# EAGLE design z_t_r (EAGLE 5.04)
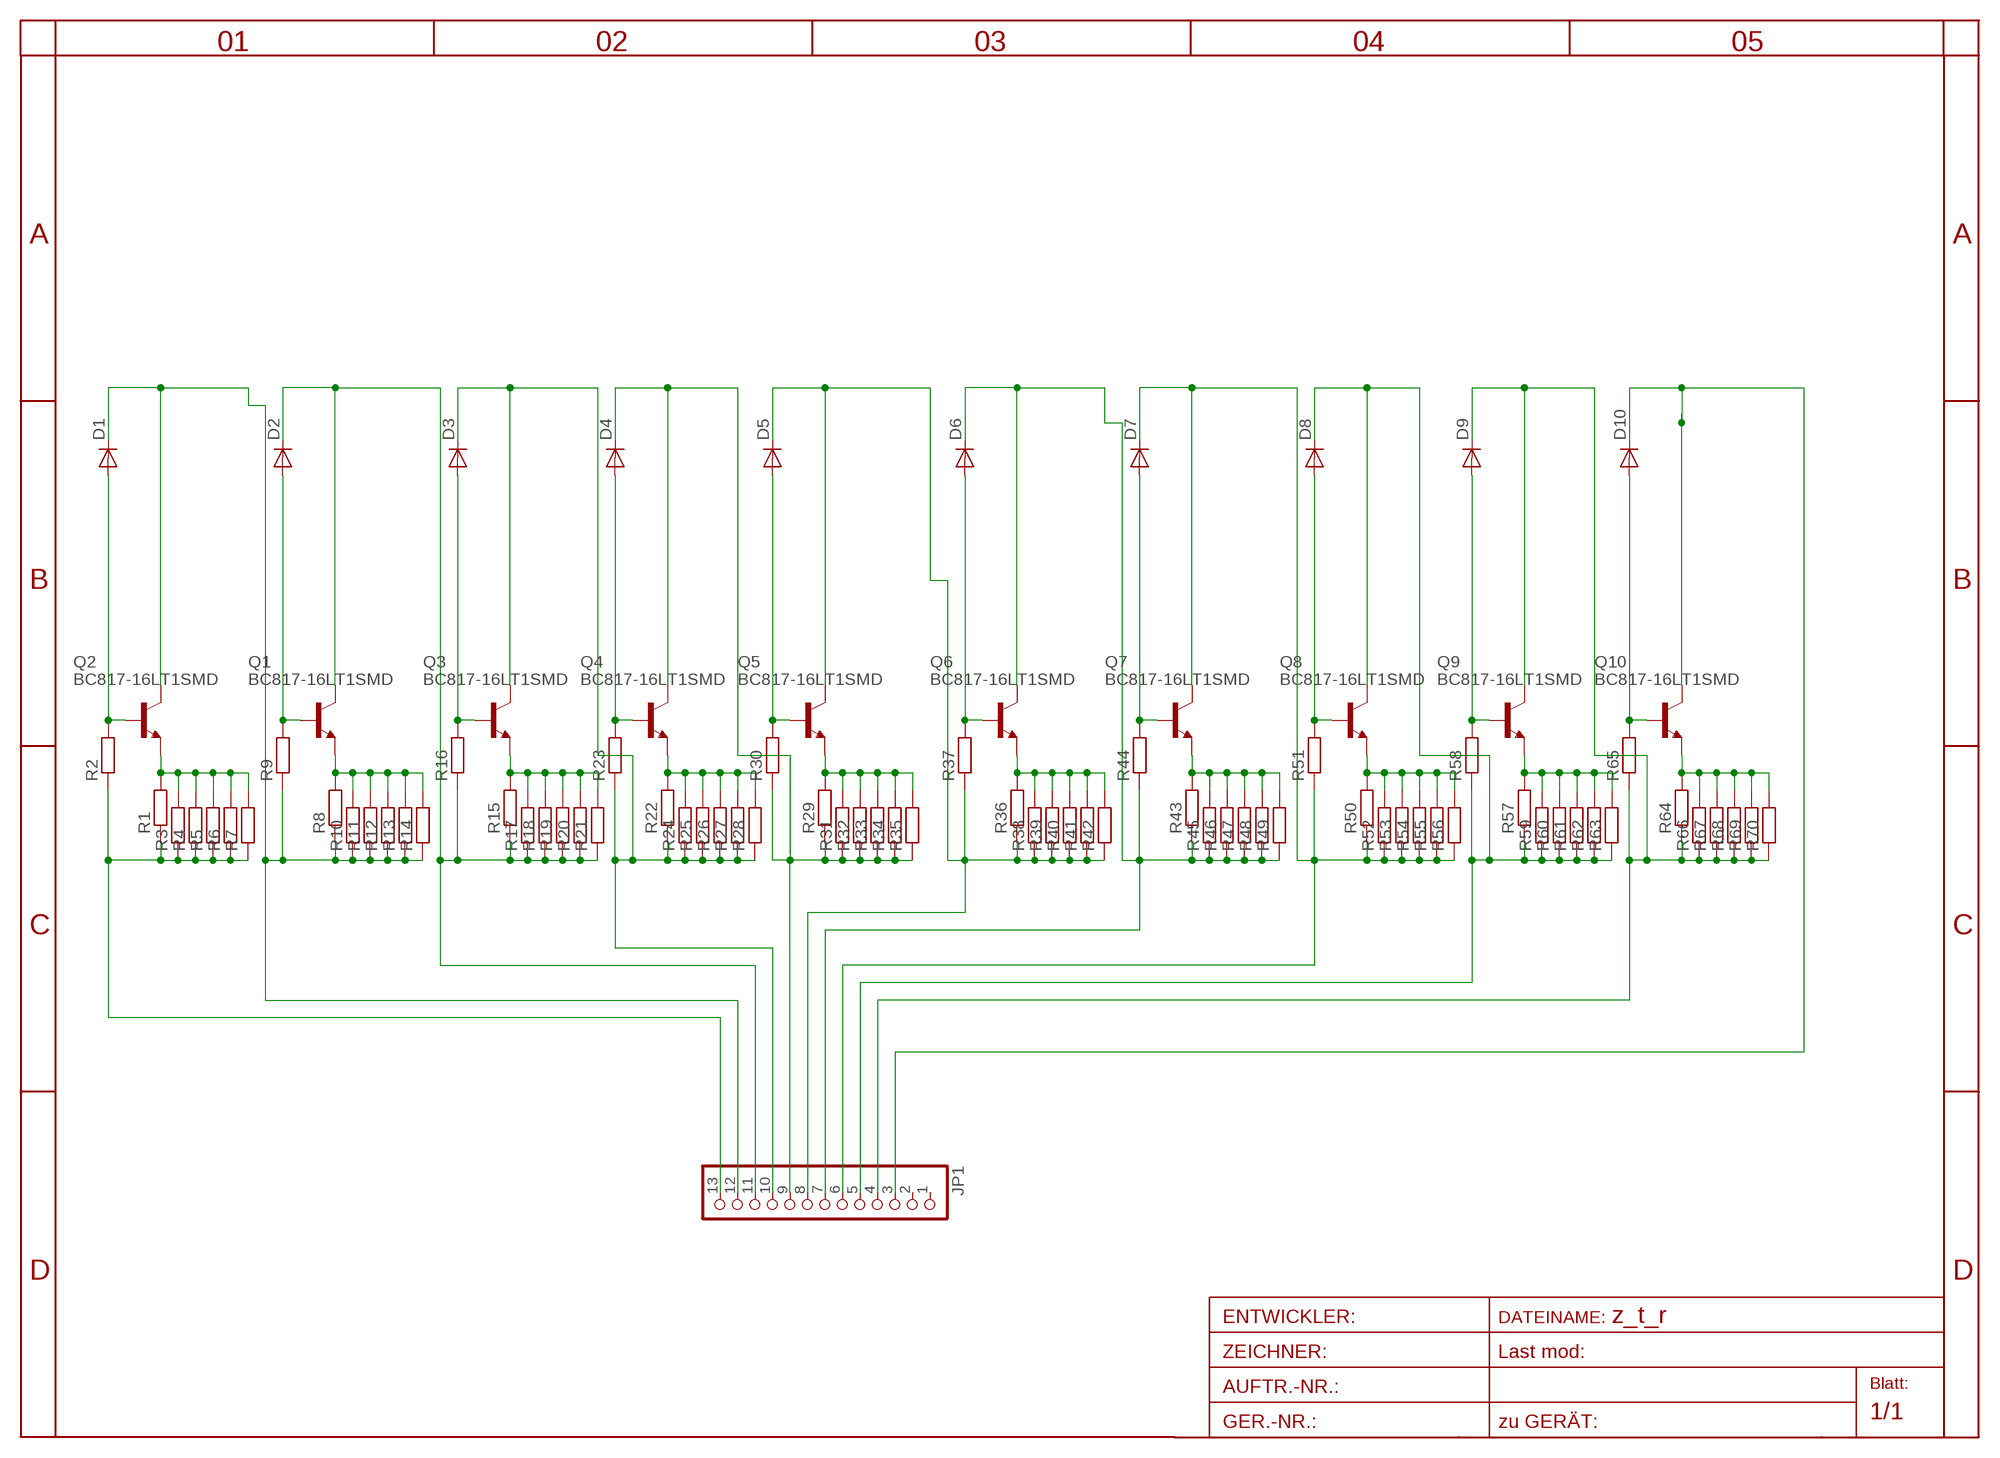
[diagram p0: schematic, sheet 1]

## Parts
D1  DIODE-MINIMELF  [MINIMELF]
D2  DIODE-MINIMELF  [MINIMELF]
D3  DIODE-MINIMELF  [MINIMELF]
D4  DIODE-MINIMELF  [MINIMELF]
D5  DIODE-MINIMELF  [MINIMELF]
D6  DIODE-MINIMELF  [MINIMELF]
D7  DIODE-MINIMELF  [MINIMELF]
D8  DIODE-MINIMELF  [MINIMELF]
D9  DIODE-MINIMELF  [MINIMELF]
D10  DIODE-MINIMELF  [MINIMELF]
JP1  PINHD-1X13  [1X13]
Q1  BC817-16LT1SMD  [SOT23-BEC]
Q2  BC817-16LT1SMD  [SOT23-BEC]
Q3  BC817-16LT1SMD  [SOT23-BEC]
Q4  BC817-16LT1SMD  [SOT23-BEC]
Q5  BC817-16LT1SMD  [SOT23-BEC]
Q6  BC817-16LT1SMD  [SOT23-BEC]
Q7  BC817-16LT1SMD  [SOT23-BEC]
Q8  BC817-16LT1SMD  [SOT23-BEC]
Q9  BC817-16LT1SMD  [SOT23-BEC]
Q10  BC817-16LT1SMD  [SOT23-BEC]
R1  R-EU_R1206  [R1206]
R2  R-EU_R0805  [R0805]
R3  R-EU_R1206  [R1206]
R4  R-EU_R1206  [R1206]
R5  R-EU_R1206  [R1206]
R6  R-EU_R1206  [R1206]
R7  R-EU_R1206  [R1206]
R8  R-EU_R1206  [R1206]
R9  R-EU_R0805  [R0805]
R10  R-EU_R1206  [R1206]
R11  R-EU_R1206  [R1206]
R12  R-EU_R1206  [R1206]
R13  R-EU_R1206  [R1206]
R14  R-EU_R1206  [R1206]
R15  R-EU_R1206  [R1206]
R16  R-EU_R0805  [R0805]
R17  R-EU_R1206  [R1206]
R18  R-EU_R1206  [R1206]
R19  R-EU_R1206  [R1206]
R20  R-EU_R1206  [R1206]
R21  R-EU_R1206  [R1206]
R22  R-EU_R1206  [R1206]
R23  R-EU_R0805  [R0805]
R24  R-EU_R1206  [R1206]
R25  R-EU_R1206  [R1206]
R26  R-EU_R1206  [R1206]
R27  R-EU_R1206  [R1206]
R28  R-EU_R1206  [R1206]
R29  R-EU_R1206  [R1206]
R30  R-EU_R0805  [R0805]
R31  R-EU_R1206  [R1206]
R32  R-EU_R1206  [R1206]
R33  R-EU_R1206  [R1206]
R34  R-EU_R1206  [R1206]
R35  R-EU_R1206  [R1206]
R36  R-EU_R1206  [R1206]
R37  R-EU_R0805  [R0805]
R38  R-EU_R1206  [R1206]
R39  R-EU_R1206  [R1206]
R40  R-EU_R1206  [R1206]
R41  R-EU_R1206  [R1206]
R42  R-EU_R1206  [R1206]
R43  R-EU_R1206  [R1206]
R44  R-EU_R0805  [R0805]
R45  R-EU_R1206  [R1206]
R46  R-EU_R1206  [R1206]
R47  R-EU_R1206  [R1206]
R48  R-EU_R1206  [R1206]
R49  R-EU_R1206  [R1206]
R50  R-EU_R1206  [R1206]
R51  R-EU_R0805  [R0805]
R52  R-EU_R1206  [R1206]
R53  R-EU_R1206  [R1206]
R54  R-EU_R1206  [R1206]
R55  R-EU_R1206  [R1206]
R56  R-EU_R1206  [R1206]
R57  R-EU_R1206  [R1206]
R58  R-EU_R0805  [R0805]
R59  R-EU_R1206  [R1206]
R60  R-EU_R1206  [R1206]
R61  R-EU_R1206  [R1206]
R62  R-EU_R1206  [R1206]
R63  R-EU_R1206  [R1206]
R64  R-EU_R1206  [R1206]
R65  R-EU_R0805  [R0805]
R66  R-EU_R1206  [R1206]
R67  R-EU_R1206  [R1206]
R68  R-EU_R1206  [R1206]
R69  R-EU_R1206  [R1206]
R70  R-EU_R1206  [R1206]

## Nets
B1: D1.C JP1.12 Q2.C R8.1 R9.1 R10.1 R11.1 R12.1 R13.1 R14.1
B2: D2.C JP1.11 Q1.C R15.1 R16.1 R17.1 R18.1 R19.1 R20.1 R21.1
B3: D3.C JP1.10 Q3.C R22.1 R23.1 R24.1 R25.1 R26.1 R27.1 R28.1
B4: D4.C JP1.9 Q4.C R29.1 R30.1 R31.1 R32.1 R33.1 R34.1 R35.1
B5: D5.C JP1.8 Q5.C R36.1 R37.1 R38.1 R39.1 R40.1 R41.1 R42.1
B6: D6.C JP1.7 Q6.C R43.1 R44.1 R45.1 R46.1 R47.1 R48.1 R49.1
B7: D7.C JP1.6 Q7.C R50.1 R51.1 R52.1 R53.1 R54.1 R55.1 R56.1
B8: D8.C JP1.5 Q8.C R57.1 R58.1 R59.1 R60.1 R61.1 R62.1 R63.1
B9: D9.C JP1.4 Q9.C R64.1 R65.1 R66.1 R67.1 R68.1 R69.1 R70.1
B10: D10.C JP1.3 Q10.C
B-: JP1.13 R1.1 R2.1 R3.1 R4.1 R5.1 R6.1 R7.1
D0: D1.A Q2.B R2.2
D1: D2.A Q1.B R9.2
D2: D3.A Q3.B R16.2
D3: D4.A Q4.B R23.2
D4: D5.A Q5.B R30.2
D5: D6.A Q6.B R37.2
D6: D7.A Q7.B R44.2
D7: D8.A Q8.B R51.2
D8: D9.A Q9.B R58.2
D9: D10.A Q10.B R65.2
N$2: Q2.E R1.2 R3.2 R4.2 R5.2 R6.2 R7.2
N$3: Q1.E R8.2 R10.2 R11.2 R12.2 R13.2 R14.2
N$6: Q3.E R15.2 R17.2 R18.2 R19.2 R20.2 R21.2
N$8: Q4.E R22.2 R24.2 R25.2 R26.2 R27.2 R28.2
N$10: Q5.E R29.2 R31.2 R32.2 R33.2 R34.2 R35.2
N$12: Q6.E R36.2 R38.2 R39.2 R40.2 R41.2 R42.2
N$14: Q7.E R43.2 R45.2 R46.2 R47.2 R48.2 R49.2
N$16: Q8.E R50.2 R52.2 R53.2 R54.2 R55.2 R56.2
N$18: Q9.E R57.2 R59.2 R60.2 R61.2 R62.2 R63.2
N$20: Q10.E R64.2 R66.2 R67.2 R68.2 R69.2 R70.2
Unconnected: JP1.1 JP1.2

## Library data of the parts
D1-D10 = diode-1:DIODE-: DIODE
JP1 = pinhead(2):PINHD-1X13: PIN HEADER
Q1-Q10 = transistor-npn:BC817*: NPN Transistor
R1-R70 = rcl-2:R-EU_: RESISTOR, European symbol

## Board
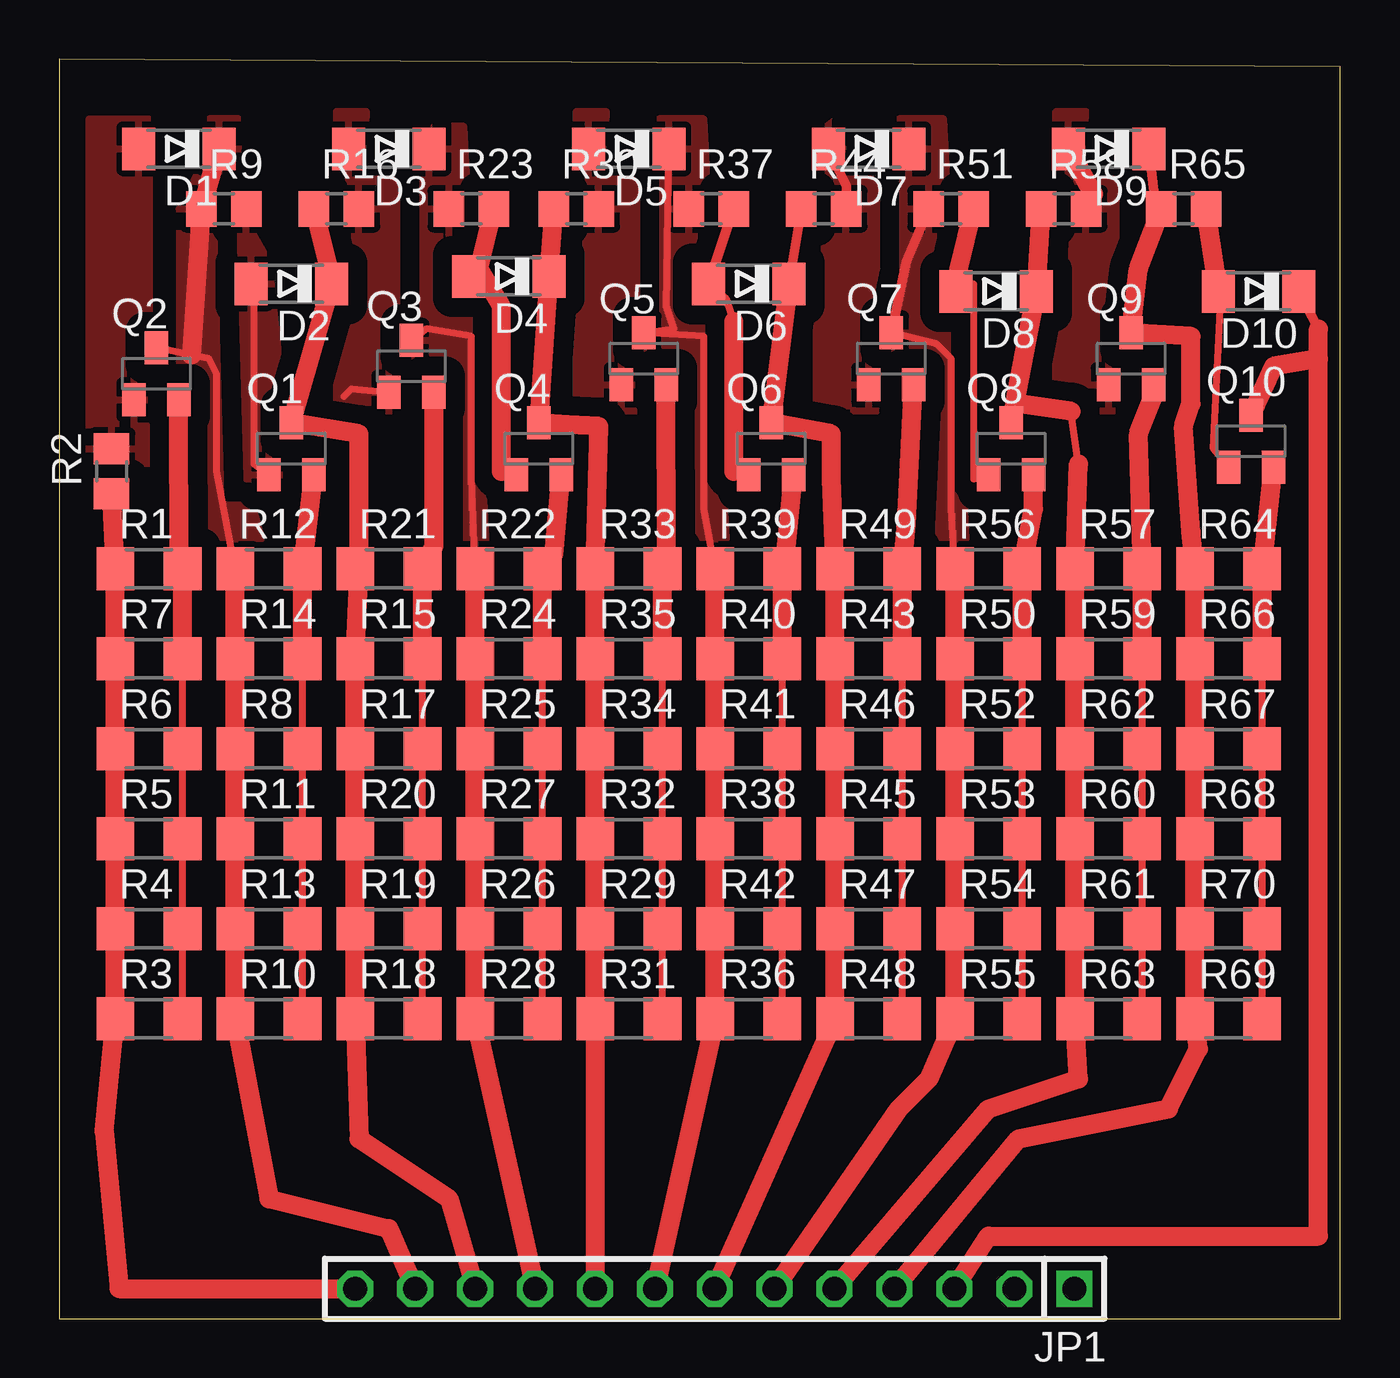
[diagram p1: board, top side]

Size 54.27 x 53.33 mm. Coordinates in mm from the lower left corner, seen from the top.
Outline: 0,0 54.27,0 54.27,53 0,53.33 0,0
Copper layers (1*16): Top 0.035mm / dielectric 1.5mm / Bottom 0.035mm
Design rules "default": minimum track width 10mil, minimum drill 24mil, track to track 8mil, track to pad 8mil, pad to pad 8mil, via to via 8mil, smd to smd 8mil, copper to edge 40mil, drill to drill 8mil, minimum pad ring 10mil, minimum via ring 8mil, stop-mask expansion 4mil, vias tented up to drill 0mil, thermal gap 10mil

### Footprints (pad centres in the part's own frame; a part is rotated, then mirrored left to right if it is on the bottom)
MINIMELF = smd 1.4 x 1.8: A 1.7,0; C -1.7,0
1X13 = drill 1.016 square: 1 -15.24,0 | drill 1.016 octagon: 2 -12.7,0; 3 -10.16,0; 4 -7.62,0; 5 -5.08,0; 6 -2.54,0; 7 0,0; 8 2.54,0; 9 5.08,0; 10 7.62,0; 11 10.16,0; 12 12.7,0; 13 15.24,0
SOT23-BEC = smd 1 x 1.4: B -0.95,-1.1; C 0,1.1; E 0.95,-1.1
R1206 = smd 1.6 x 1.803: 1 -1.422,0; 2 1.422,0
R0805 = smd 1.3 x 1.5: 1 -0.95,0; 2 0.95,0

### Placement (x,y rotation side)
D1  5.08,49.53 180 top
D2  9.84,43.81 180 top
D3  13.97,49.53 180 top
D4  19.05,44.13 180 top
D5  24.13,49.53 180 top
D6  29.21,43.81 180 top
D7  34.29,49.53 180 top
D8  39.69,43.5 180 top
D9  44.45,49.53 180 top
D10  50.8,43.5 180 top
JP1  27.77,1.27 180 top
Q1  9.84,36.83 0 top
Q2  4.13,40.01 0 top
Q3  14.92,40.32 0 top
Q4  20.32,36.83 0 top
Q5  24.77,40.64 0 top
Q6  30.16,36.83 0 top
Q7  35.24,40.64 0 top
Q8  40.32,36.83 0 top
Q9  45.4,40.64 0 top
Q10  50.48,37.15 0 top
R1  3.81,31.75 0 top
R2  2.22,35.88 90 top
R3  3.81,12.7 0 top
R4  3.81,16.51 0 top
R5  3.81,20.32 0 top
R6  3.81,24.13 0 top
R7  3.81,27.94 0 top
R8  8.89,24.13 0 top
R9  6.98,46.99 0 top
R10  8.89,12.7 0 top
R11  8.89,20.32 0 top
R12  8.89,31.75 0 top
R13  8.89,16.51 0 top
R14  8.89,27.94 0 top
R15  13.97,27.94 0 top
R16  11.75,46.99 0 top
R17  13.97,24.13 0 top
R18  13.97,12.7 0 top
R19  13.97,16.51 0 top
R20  13.97,20.32 0 top
R21  13.97,31.75 0 top
R22  19.05,31.75 0 top
R23  17.46,46.99 0 top
R24  19.05,27.94 0 top
R25  19.05,24.13 0 top
R26  19.05,16.51 0 top
R27  19.05,20.32 0 top
R28  19.05,12.7 0 top
R29  24.13,16.51 0 top
R30  21.91,46.99 0 top
R31  24.13,12.7 0 top
R32  24.13,20.32 0 top
R33  24.13,31.75 0 top
R34  24.13,24.13 0 top
R35  24.13,27.94 0 top
R36  29.21,12.7 0 top
R37  27.62,46.99 0 top
R38  29.21,20.32 0 top
R39  29.21,31.75 0 top
R40  29.21,27.94 0 top
R41  29.21,24.13 0 top
R42  29.21,16.51 0 top
R43  34.29,27.94 0 top
R44  32.38,46.99 0 top
R45  34.29,20.32 0 top
R46  34.29,24.13 0 top
R47  34.29,16.51 0 top
R48  34.29,12.7 0 top
R49  34.29,31.75 0 top
R50  39.37,27.94 0 top
R51  37.78,46.99 0 top
R52  39.37,24.13 0 top
R53  39.37,20.32 0 top
R54  39.37,16.51 0 top
R55  39.37,12.7 0 top
R56  39.37,31.75 0 top
R57  44.45,31.75 0 top
R58  42.55,46.99 0 top
R59  44.45,27.94 0 top
R60  44.45,20.32 0 top
R61  44.45,16.51 0 top
R62  44.45,24.13 0 top
R63  44.45,12.7 0 top
R64  49.53,31.75 0 top
R65  47.62,46.99 0 top
R66  49.53,27.94 0 top
R67  49.53,24.13 0 top
R68  49.53,20.32 0 top
R69  49.53,12.7 0 top
R70  49.53,16.51 0 top

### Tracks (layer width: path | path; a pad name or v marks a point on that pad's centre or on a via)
B1
  Top 0.305: Q2.C 5.61,40.79 6.35,40.64 6.67,40.01 6.67,35.88 R12.1
  Top 0.813: R12.1 R14.1 R8.1 R11.1 R13.1 R10.1 8.89,5.08 13.97,3.81 JP1.12 | D1.C R9.1 5.61,40.79
  pour Top (isolate 0.813, rank 2): 6.35,50.8 6.35,49.53 5.08,46.99 5.08,33.02 8.57,33.02 7.3,37.78 7.62,50.8
B2
  Top 0.813: 12.7,31.75 12.7,37.47 Q1.C D2.C 11.43,44.45 R16.1 | 12.7,31.75 R21.1 | 12.7,31.75 R15.1 R17.1 R20.1 R19.1 R18.1 12.7,7.62 16.51,5.08 JP1.11
B3
  Top 0.305: R22.1 17.46,35.56 17.46,41.59 15.56,41.91 Q3.C
  Top 0.813: R22.1 R24.1 R25.1 R27.1 R26.1 R28.1 JP1.10
  pour Top (isolate 0.813, rank 2): 15.88,50.48 15.88,49.21 14.61,46.67 14.61,32.7 18.1,32.7 17.14,50.48
B4
  Top 0.813: R30.1 D4.C Q4.C 21.57,37.85 22.86,37.78 R33.1 R35.1 R34.1 R32.1 R29.1 R31.1 JP1.9
B5
  Top 0.305: D5.C 25.72,42.86 26.04,41.91 Q5.C 27.3,41.59 27.3,34.29 R39.1
  Top 0.813: R39.1 R40.1 R41.1 R38.1 R42.1 R36.1 JP1.8
  pour Top (isolate 0.813, rank 2): 25.4,50.8 25.4,49.53 24.13,46.99 24.13,33.02 28.26,33.02 27.3,50.8
B6
  Top 0.406: D6.C R44.1
  Top 0.813: D6.C Q6.C 32.7,37.47 32.7,35.56 R49.1 R43.1 R46.1 R45.1 R47.1 R48.1 JP1.7
B7
  Top 0.305: R56.1 37.78,34.29 37.78,40.64 37.15,41.27 Q7.C
  Top 0.406: R51.1 35.88,44.77 Q7.C
  Top 0.813: R56.1 R50.1 R52.1 R53.1 R54.1 R55.1 36.83,10.16 35.56,8.89 JP1.6
  pour Top (isolate 0.813, rank 2): 35.56,50.8 35.56,49.53 34.29,46.99 34.29,33.02 38.42,33.02 37.47,50.8
B8
  Top 0.305: 43.18,36.2 42.86,38.42
  Top 0.813: 43.18,36.2 R57.1 R59.1 R62.1 R60.1 R61.1 R63.1 43.18,10.16 39.37,8.89 JP1.5 | 40.48,38.77 Q8.C | 40.48,38.77 D8.C R58.1 | 42.86,38.42 40.48,38.77
B9
  Top 0.406: R65.1 46.36,47.73 D9.C
  Top 0.813: R65.1 45.72,44.45 Q9.C 47.94,41.59 47.94,38.73 47.62,37.78 47.94,33.34 R64.1 R66.1 R67.1 R68.1 R70.1 R69.1 48.26,11.43 46.99,8.89 40.64,7.62 JP1.4
B10
  Top 0.406: 53.34,41.91 D10.C
  Top 0.813: JP1.3 39.37,3.49 53.34,3.49 53.34,40.64 | 53.34,40.64 53.34,41.91 | Q10.C 51.44,40.32 53.34,40.64
B-
  Top 0.813: JP1.13 2.54,1.27 1.91,7.94 R3.1 R4.1 R5.1 R6.1 R7.1 R1.1 R2.1
D0
  pour Top (isolate 0.813): 1.27,50.8 3.81,50.8 3.81,40.64 3.81,33.02 1.27,33.02
D1
  Top 0.305: Q1.B 8.26,36.2 8.26,43.81 8.57,44.13 D2.A
  pour Top (isolate 0.813): 7.62,46.99 7.94,35.56 9.84,35.56 8.89,44.77
D2
  Top 0.305: 12.06,39.05 12.38,39.37 Q3.B
  pour Top (isolate 0.813): 11.75,51.12 13.02,51.12 12.7,48.26 14.29,48.26 14.29,38.42 11.75,38.42
D3
  Top 0.305: 17.78,44.45 D4.A | 18.73,35.88 Q4.B
  Top 0.813: 18.73,35.88 18.73,42.86 17.78,44.45 R23.2
D4
  pour Top (isolate 0.813): 21.91,51.12 23.18,51.12 22.86,48.26 24.45,48.26 24.45,38.42 21.91,38.42
D5
  Top 0.305: 28.57,35.88 Q6.B | 28.57,42.23 28.26,43.18 D6.A
  Top 0.406: D6.A R37.2
  Top 0.813: 28.57,35.88 28.57,42.23
D6
  Top 0.406: D7.A 33.34,47.94 R44.2
  pour Top (isolate 0.813): 32.07,50.16 33.34,51.12 33.02,48.26 34.61,48.26 34.61,38.42 32.07,38.42
D7
  Top 0.305: D8.A 38.74,43.81 38.74,35.56 Q8.B
  Top 0.406: D8.A 38.1,44.45
  Top 0.813: 38.1,44.45 R51.2
D8
  Top 0.813: D9.A 43.82,47.62 R58.2
  pour Top (isolate 0.813): 42.23,51.12 43.5,51.12 43.18,48.26 44.77,48.26 44.77,38.42 42.23,38.42
D9
  Top 0.305: D10.A 49.21,43.18 48.9,36.83 Q10.B
  Top 0.813: D10.A R65.2
N$2
  Top 0.305: R3.2 R4.2 R5.2 R6.2 R7.2
  Top 0.813: Q2.E 5.08,31.75 R1.2 R7.2
N$3
  Top 0.305: R14.2 R8.2 R11.2 R13.2 R10.2
  Top 0.813: Q1.E R12.2 R14.2
N$6
  Top 0.305: R18.2 R19.2 R20.2 R17.2 R15.2
  Top 0.813: Q3.E 15.88,38.1 15.88,32.7 R21.2 R15.2
N$8
  Top 0.305: R22.2 20.95,32.38 | R28.2 R26.2 R27.2 R25.2 R24.2
  Top 0.813: 20.95,32.38 Q4.E | R24.2 R22.2
N$10
  Top 0.305: R33.2 25.72,32.38 | R31.2 R29.2 R32.2 R34.2 R35.2
  Top 0.813: 25.72,32.38 Q5.E | R35.2 R33.2
N$12
  Top 0.305: R39.2 30.8,32.7 | R40.2 R41.2 R38.2 R42.2 R36.2
  Top 0.813: 30.8,32.7 Q6.E | R40.2 R39.2
N$14
  Top 0.305: R48.2 R47.2 R45.2 R46.2 R43.2
  Top 0.813: R43.2 R49.2 35.88,33.66 Q7.E
N$16
  Top 0.305: R50.2 R52.2 R53.2 R54.2 R55.2
  Top 0.813: R50.2 R56.2 41.28,34.29 Q8.E
N$18
  Top 0.305: 46.36,39.05 Q9.E | R63.2 R61.2 R60.2 R62.2 R59.2
  Top 0.813: R59.2 R57.2 45.72,37.47 46.36,39.05
N$20
  Top 0.305: R66.2 R67.2 R68.2 R70.2 R69.2
  Top 0.813: Q10.E R64.2 R66.2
